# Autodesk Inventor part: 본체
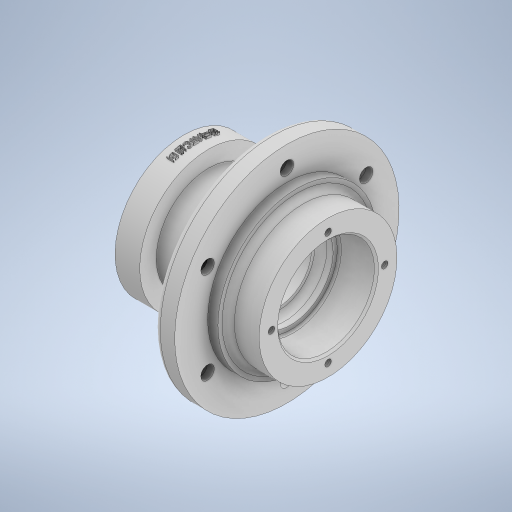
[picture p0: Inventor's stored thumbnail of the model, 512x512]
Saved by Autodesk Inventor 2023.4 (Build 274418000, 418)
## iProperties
Created: 2024-04
Part Number: 본체
Material: 일반
Document SubType Name: Modeling
Designer: Edu03
Density: 1 g/cm^3
Appearance: 기본값
Author: Edu03
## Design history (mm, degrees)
sketch "스케치2"
  geometry: L1 (0, 0)-(0, 33.5); L2 (0, 33.5)-(12, 33.5); L3 (12, 33.5)-(12, 25.5); L4 (12, 25.5)-(40, 25.5); L5 (40, 25.5)-(40, 54.5); L6 (40, 54.5)-(50, 54.5); L7 (50, 54.5)-(50, 38.5); L8 (50, 38.5)-(55, 38.5); L9 (55, 38.5)-(55, 33.5); L10 (55, 33.5)-(70, 33.5); L11 (70, 33.5)-(70, 0); L12 (70, 0)-(0, 0); L13 (-45.271, 0)-(93.894, 0); 1 further point
  constraints: 26 end point, 11 perpendicular, 1 collinear, 1 horizontal, 1 midpoint, 1 vertical
  dimensions: "d1" = 33.5 distance of L1.start L1.end; "d2" = 12 distance of L1.end L2.end; "d3" = 10 distance of L5.end L6.end; "d4" = 20 distance between parallel lines of L7 L11; "d5" = 70 distance between parallel lines of L11 L1; "d6" = 5 distance of L8.end L7.end; "d7" = 33.5 distance of L10.end L11.end; "d8" = 38.5 distance from line of L12 point (52.5, 38.5); "d9" = 109 diameter of L6 L13; "d10" = 51 diameter of L4 L13
revolve "회전1" sketch "스케치2" stored, may be unused: angle "d11" = 90 deg
sketch "스케치3"
  geometry: L1 (0, 33.5)-(12, 33.5) reference; L2 (12, -33.5)-(12, 33.5) reference; L3 (12, 25.5)-(40, 25.5) reference; L4 (40, 54.5)-(50, 54.5) reference; L5 (50, 38.5)-(55, 38.5) reference; L6 (55, 33.5)-(70, 33.5) reference; L7 (70, -33.5)-(70, 33.5) reference; L8 (0, 0)-(0, 23.5); L9 (1, 23.5)-(17, 23.5); L10 (18, 22.5)-(18, 20.5); L11 (18, 20.5)-(21, 20.5); L12 (24, 17.5)-(24, 16); L13 (24, 16)-(35, 16); L14 (35, 62.204)-(35, -35.561); L15 (35, 16)-(35, 0); L16 (35, 0)-(0, 0); L17 (-11.867, 0)-(53.756, 0); L18 (0, 24.5)-(0, 32.098); L19 (0, -33.5)-(0, 33.5) reference; L20 (1, 23.5)-(0, 24.5); L21 (0, 23.5)-(0, 24.5); L22 (46, 16)-(35, 16); L23 (46, 17.5)-(46, 16); L24 (52, 20.5)-(49, 20.5); L25 (52, 22.5)-(52, 20.5); L26 (69, 23.5)-(53, 23.5); L27 (70, 0)-(70, 23.5); L28 (69, 23.5)-(70, 24.5); L29 (70, 24.5)-(70, 32.098); L30 (70, 23.5)-(70, 24.5); L31 (35, 0)-(70, 0); A1 r 1 centre (17, 22.5) between (18, 22.5) and (17, 23.5); A2 r 3 centre (21, 17.5) between (24, 17.5) and (21, 20.5); A3 r 3 centre (49, 17.5) between (49, 20.5) and (46, 17.5); A4 r 1 centre (53, 22.5) between (53, 23.5) and (52, 22.5); 9 further points
  constraints: 46 end point, 16 symmetric about line, 8 point on circle, 5 point on line, 4 centre point, 4 perpendicular, 4 tangent, 3 collinear, 3 horizontal, 1 midpoint, 1 vertical, 2 other
  dimensions: "d14" = 23.5 distance of L8.start L8.end; "d15" = 20.5 distance between parallel lines of L16 L11; "d16" = 16 distance between parallel lines of L16 L13; "d17" = 18 distance from line of point (18, 21.5) L8; "d18" = 6 distance between parallel lines of L12 L10; "d20" = 1 radius of A1 (derived); "d21" = 3 radius of A2; "d22" = 1 distance of L9.start L8.end; "d23" = 1 distance of L18.start L8.end (= d22)
revolve "회전2" sketch "스케치3" stored, may be unused: angle "d24" = 90 deg
sketch "스케치4"
  geometry: 1 further point
sketch "스케치5"
  geometry: A1 r 27.5 centre (0, 0) between (27.5, 0) and (-27.5, 0); 3 further points
  constraints: 4 point on circle, 1 centre point, 1 coincident
  dimensions: "d25" = 55 diameter of A1
hole "구멍1" sketch "스케치5" at (0, 27.5), (27.5, 0), (0, -27.5), (-27.5, 0) diameter "d26" = 3.242; stored, may be unused: countersink angle "d30" = 82 deg, drill point angle "d32" = 118 deg; dims "d27" = 8, "d28" = 3.023, "d29" = 2, "d31" = 10
sketch "스케치6"
  geometry: C1 r 1.621 at (-27.5, 0) reference; C2 r 1.621 at (0, -27.5) reference; A1 r 27.5 centre (0, 0) between (27.5, 0) and (0, 27.5); 3 further points
  constraints: 3 coincident, 2 point on circle, 1 centre point
  dimensions: "d33" = 55 diameter of A1
hole "구멍2" sketch "스케치6" at (27.5, 0), (0, 27.5), (-27.5, 0), (0, -27.5) diameter "d34" = 3.242; stored, may be unused: countersink angle "d38" = 90 deg, drill point angle "d40" = 118 deg; dims "d35" = 8, "d36" = 4, "d37" = 2, "d39" = 10
sketch "스케치7" dims "d41" = 89
  geometry: L1 (0, 0)-(-38.538, 22.25); L2 (0, 0)-(38.538, 22.25); L3 (0, 0)-(38.538, -22.25); L4 (0, 0)-(-38.538, -22.25); L5 (0, 44.5)-(0, -44.5); C1 r 54.5 at (0, 0) reference; C2 r 33.5 at (0, 0) reference; 7 further points
  constraints: 10 end point, 5 coincident, 1 vertical, 9 other
  dimensions: "d42" = 60 deg angle of L1 L5; "d43" = 60 deg angle of L4 L1; "d44" = 60 deg angle of L2 L5; "d45" = 60 deg angle of L3 L2
hole "구멍3" sketch "스케치7" at (0, 44.5), (38.538, 22.25), (38.538, -22.25), (0, -44.5), (-38.538, -22.25), (-38.538, 22.25) diameter "d46" = 6.6; stored, may be unused: countersink angle "d50" = 90 deg, drill point angle "d52" = 118 deg; dims "d47" = 8, "d48" = 11, "d49" = 6.6, "d51" = 10
fillet "모깎기1" dims "d53" = 3
fillet "모깎기2" dims "d54" = 3
node "작업 평면1"
sketch "스케치8"
  geometry: L1 (-12, 33.5)-(-12, -33.5) reference; L2 (0, -33.5)-(-12, -33.5) reference; L3 (0, 33.5)-(0, -33.5) reference; L4 (0, 33.5)-(-12, 33.5) reference; 1 further point
sketch "스케치10"
  geometry: L1 (-7.158, -11.225)-(-7.158, -2.052); L2 (-7.158, -2.052)-(26.799, -2.052); L3 (26.799, -2.052)-(26.799, -11.225); L4 (26.799, -11.225)-(-7.158, -11.225); 1 further point
  constraints: 2 other
feature "엠보싱1" sketch "스케치10" dims "d1" = 33.5, "d2" = 12, "d3" = 10, "d4" = 20, "d5" = 70, "d6" = 5, "d7" = 33.5, "d8" = 38.5, "d9" = 109, "d10" = 51, "d56" = 1, "d57" = 0
sketch "스케치13"
  geometry: 1 further point
node "솔리드1"
feature "A9D066F2-1C7D-4E18-AEED-F7BC21143FA4" dims "d46" = 6.6, "d47" = 8, "d48" = 11, "d49" = 6.6, "d50" = 90 deg, "d51" = 10, "d52" = 118 deg
other parameters: "d55" = 74.5
